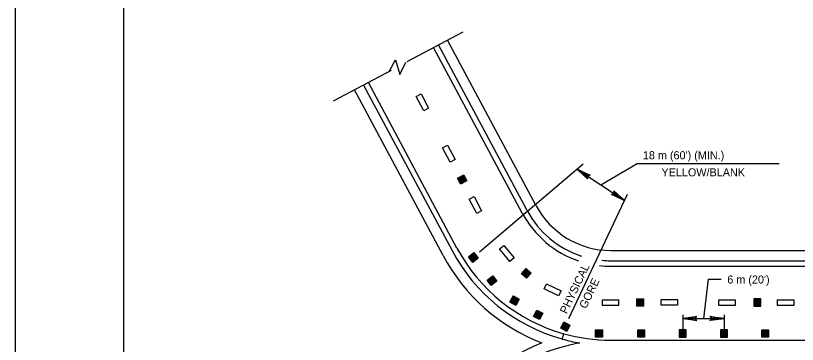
# Model space of a CAD drawing. Extents: x 639362 to 641108, y 298458 to 299646.
# Drawn here: x 639362.3 to 639652.3, y 299227.7 to 299349.9 of the extents above; entities that cross this region are included whole.
import ezdxf

# ---------------------------------------------------------------- set-up
doc = ezdxf.new("R2010")
doc.units = 0
for name, color, linetype in [('1', 7, 'Continuous'), ('2', 7, 'Continuous'), ('PLT-BNDY', 7, 'Continuous')]:
    doc.layers.add(name, color=color, linetype=linetype)

msp = doc.modelspace()

# ---------------------------------------------------------------- linework, layer by layer
at = {"layer": '1'}
msp.add_line((639402.31, 299630.63), (639402.31, 299066.63), dxfattribs=at)
at = {"layer": '2'}
for p, q in [((639507.56, 299332.75), (639528.33, 299343.84)), ((639555.38, 299279.23), (639522.52, 299340.74)), ((639550.22, 299276.47), (639517.36, 299337.98)), ((639552.04, 299277.45), (639519.18, 299338.95)), ((639480.23, 299318.14), (639501.69, 299329.61)), ((639493.13, 299325.03), (639491.31, 299324.06)), ((639491.31, 299324.06), (639524.18, 299262.56)), ((639526, 299263.53), (639493.13, 299325.03)), ((639520.84, 299260.77), (639487.97, 299322.28)), ((639510.86, 299319.82), (639512.69, 299320.78)), ((639513.67, 299314.5), (639510.86, 299319.82)), ((639512.69, 299320.78), (639515.49, 299315.46)), ((639515.49, 299315.46), (639513.67, 299314.5)), ((639520.7, 299300.75), (639522.53, 299301.71)), ((639523.5, 299295.43), (639520.7, 299300.75)), ((639522.53, 299301.71), (639525.33, 299296.39)), ((639525.33, 299296.39), (639523.5, 299295.43)), ((639534.31, 299262.09), (639572.85, 299294.76)), ((639579.34, 299287), (639592.87, 299294.89)), ((639592.87, 299294.89), (639645.57, 299294.89)), ((639526.16, 299289.48), (639528.5, 299290.73)), ((639526.36, 299289.38), (639528.47, 299290.51)), ((639528.47, 299290.51), (639529.48, 299288.63)), ((639528.5, 299290.73), (639529.68, 299288.53)), ((639570.58, 299292.84), (639588.1, 299281.16)), ((639527.34, 299287.28), (639526.16, 299289.48)), ((639527.37, 299287.5), (639526.36, 299289.38)), ((639526.6, 299289.3), (639528.4, 299290.27)), ((639527.44, 299287.74), (639526.6, 299289.3)), ((639526.84, 299289.23), (639528.33, 299290.03)), ((639527.51, 299287.98), (639526.84, 299289.23)), ((639527.08, 299289.16), (639528.25, 299289.79)), ((639527.58, 299288.22), (639527.08, 299289.16)), ((639527.32, 299289.09), (639528.18, 299289.55)), ((639527.66, 299288.46), (639527.32, 299289.09)), ((639529.68, 299288.53), (639527.34, 299287.28)), ((639529.48, 299288.63), (639527.37, 299287.5)), ((639529.24, 299288.7), (639527.44, 299287.74)), ((639529, 299288.78), (639527.51, 299287.98)), ((639527.56, 299289.01), (639528.11, 299289.31)), ((639527.73, 299288.7), (639527.56, 299289.01)), ((639528.76, 299288.85), (639527.58, 299288.22)), ((639528.52, 299288.92), (639527.66, 299288.46)), ((639528.28, 299288.99), (639527.73, 299288.7)), ((639528.04, 299289.07), (639527.8, 299288.94)), ((639528.11, 299289.31), (639528.28, 299288.99)), ((639528.18, 299289.55), (639528.52, 299288.92)), ((639528.25, 299289.79), (639528.76, 299288.85)), ((639528.33, 299290.03), (639529, 299288.78)), ((639528.4, 299290.27), (639529.24, 299288.7)), ((639530.53, 299281.68), (639532.36, 299282.65)), ((639532.36, 299282.65), (639535.16, 299277.33)), ((639567.44, 299237.37), (639589.2, 299283.5)), ((639533.34, 299276.36), (639530.53, 299281.68)), ((639535.16, 299277.33), (639533.34, 299276.36)), ((639530.27, 299260.24), (639532.21, 299261.81)), ((639530.5, 299260.26), (639532.15, 299261.6)), ((639532.15, 299261.6), (639533.66, 299259.74)), ((639532.21, 299261.81), (639533.88, 299259.75)), ((639583.1, 299262.59), (639743.31, 299262.59)), ((639531.94, 299258.18), (639530.27, 299260.24)), ((639532.01, 299258.4), (639530.5, 299260.26)), ((639530.75, 299260.23), (639532.13, 299261.35)), ((639532.03, 299258.65), (639530.75, 299260.23)), ((639531, 299260.21), (639532.1, 299261.1)), ((639532.06, 299258.9), (639531, 299260.21)), ((639531.25, 299260.18), (639532.07, 299260.85)), ((639532.08, 299259.14), (639531.25, 299260.18)), ((639531.5, 299260.15), (639532.05, 299260.6)), ((639532.11, 299259.39), (639531.5, 299260.15)), ((639531.75, 299260.13), (639532.02, 299260.35)), ((639532.14, 299259.64), (639531.75, 299260.13)), ((639533.88, 299259.75), (639531.94, 299258.18)), ((639531.99, 299260.1), (639532.16, 299259.89)), ((639533.66, 299259.74), (639532.01, 299258.4)), ((639532.02, 299260.35), (639532.41, 299259.87)), ((639533.41, 299259.77), (639532.03, 299258.65)), ((639532.05, 299260.6), (639532.66, 299259.84)), ((639533.16, 299259.79), (639532.06, 299258.9)), ((639532.07, 299260.85), (639532.91, 299259.81)), ((639532.91, 299259.81), (639532.08, 299259.14)), ((639532.1, 299261.1), (639533.16, 299259.79)), ((639532.66, 299259.84), (639532.11, 299259.39)), ((639532.13, 299261.35), (639533.41, 299259.77)), ((639532.41, 299259.87), (639532.14, 299259.64)), ((639583.09, 299258.81), (639743.31, 299258.81)), ((639549.93, 299253.95), (639551.72, 299255.91)), ((639550.15, 299253.92), (639551.77, 299255.69)), ((639551.72, 299255.91), (639553.56, 299254.22)), ((639551.77, 299255.69), (639553.34, 299254.25)), ((639583.09, 299256.74), (639743.31, 299256.74)), ((639537.18, 299251.59), (639539.3, 299253.19)), ((639537.39, 299251.52), (639539.31, 299252.96)), ((639539.3, 299253.19), (639540.8, 299251.19)), ((639539.31, 299252.96), (639540.59, 299251.26)), ((639551.77, 299252.27), (639549.93, 299253.95)), ((639551.72, 299252.48), (639550.15, 299253.92)), ((639550.41, 299253.93), (639551.78, 299255.44)), ((639551.71, 299252.74), (639550.41, 299253.93)), ((639550.65, 299253.94), (639551.79, 299255.19)), ((639551.7, 299252.99), (639550.65, 299253.94)), ((639550.9, 299253.96), (639551.8, 299254.94)), ((639551.69, 299253.24), (639550.9, 299253.96)), ((639551.15, 299253.97), (639551.81, 299254.69)), ((639551.68, 299253.49), (639551.15, 299253.97)), ((639551.41, 299253.98), (639551.83, 299254.43)), ((639551.67, 299253.74), (639551.41, 299253.98)), ((639551.84, 299254.19), (639551.66, 299253.99)), ((639552.09, 299254.19), (639551.67, 299253.74)), ((639552.34, 299254.21), (639551.68, 299253.49)), ((639552.59, 299254.22), (639551.69, 299253.24)), ((639552.84, 299254.23), (639551.7, 299252.99)), ((639553.09, 299254.24), (639551.71, 299252.74)), ((639553.34, 299254.25), (639551.72, 299252.48)), ((639553.56, 299254.22), (639551.77, 299252.27)), ((639551.78, 299255.44), (639553.09, 299254.24)), ((639551.79, 299255.19), (639552.84, 299254.23)), ((639551.8, 299254.94), (639552.59, 299254.22)), ((639551.81, 299254.69), (639552.34, 299254.21)), ((639551.83, 299254.43), (639552.09, 299254.19)), ((639538.68, 299249.6), (639537.18, 299251.59)), ((639538.67, 299249.82), (639537.39, 299251.52)), ((639537.64, 299251.49), (639539.27, 299252.72)), ((639538.71, 299250.07), (639537.64, 299251.49)), ((639537.89, 299251.45), (639539.24, 299252.47)), ((639538.74, 299250.32), (639537.89, 299251.45)), ((639538.14, 299251.42), (639539.2, 299252.22)), ((639538.78, 299250.57), (639538.14, 299251.42)), ((639538.39, 299251.39), (639539.16, 299251.97)), ((639538.81, 299250.82), (639538.39, 299251.39)), ((639538.63, 299251.35), (639539.13, 299251.72)), ((639538.85, 299251.07), (639538.63, 299251.35)), ((639540.59, 299251.26), (639538.67, 299249.82)), ((639540.8, 299251.19), (639538.68, 299249.6)), ((639540.33, 299251.3), (639538.71, 299250.07)), ((639540.09, 299251.34), (639538.74, 299250.32)), ((639539.84, 299251.37), (639538.78, 299250.57)), ((639539.59, 299251.4), (639538.81, 299250.82)), ((639539.34, 299251.44), (639538.85, 299251.07)), ((639538.88, 299251.31), (639539.1, 299251.47)), ((639539.13, 299251.72), (639539.34, 299251.44)), ((639539.16, 299251.97), (639539.59, 299251.4)), ((639539.2, 299252.22), (639539.84, 299251.37)), ((639539.24, 299252.47), (639540.09, 299251.34)), ((639539.27, 299252.72), (639540.33, 299251.3)), ((639558.31, 299248.37), (639559.21, 299250.23)), ((639559.21, 299250.23), (639564.62, 299247.61)), ((639619.18, 299251.99), (639617.48, 299237.38)), ((639619.18, 299251.99), (639624.04, 299251.99)), ((639563.72, 299245.75), (639558.31, 299248.37)), ((639564.62, 299247.61), (639563.72, 299245.75)), ((639545.66, 299243.42), (639546.95, 299245.74)), ((639545.88, 299243.45), (639547.05, 299245.54)), ((639546.12, 299243.52), (639547.12, 299245.3)), ((639546.36, 299243.59), (639547.19, 299245.06)), ((639546.6, 299243.65), (639547.25, 299244.82)), ((639546.84, 299243.72), (639547.32, 299244.58)), ((639546.95, 299245.74), (639549.13, 299244.52)), ((639547.05, 299245.54), (639548.91, 299244.5)), ((639547.09, 299243.79), (639547.39, 299244.33)), ((639547.12, 299245.3), (639548.66, 299244.43)), ((639547.19, 299245.06), (639548.42, 299244.37)), ((639547.25, 299244.82), (639548.18, 299244.3)), ((639547.32, 299244.58), (639547.94, 299244.23)), ((639547.33, 299243.86), (639547.46, 299244.09)), ((639547.39, 299244.33), (639547.7, 299244.16)), ((639547.7, 299244.16), (639547.4, 299243.62)), ((639547.94, 299244.23), (639547.47, 299243.38)), ((639548.18, 299244.3), (639547.53, 299243.13)), ((639548.42, 299244.37), (639547.6, 299242.89)), ((639548.66, 299244.43), (639547.67, 299242.65)), ((639548.91, 299244.5), (639547.74, 299242.41)), ((639549.13, 299244.52), (639547.83, 299242.2)), ((639592.74, 299244.59), (639595.23, 299244.59)), ((639592.74, 299241.93), (639592.74, 299244.59)), ((639592.92, 299244.45), (639595.05, 299244.45)), ((639592.92, 299242.06), (639592.92, 299244.45)), ((639593.1, 299244.28), (639594.87, 299244.28)), ((639593.1, 299242.24), (639593.1, 299244.28)), ((639593.28, 299244.1), (639594.7, 299244.1)), ((639593.28, 299242.41), (639593.28, 299244.1)), ((639594.7, 299244.1), (639594.7, 299242.41)), ((639594.87, 299244.28), (639594.87, 299242.24)), ((639595.05, 299244.45), (639595.05, 299242.06)), ((639595.23, 299244.59), (639595.23, 299241.93)), ((639601.74, 299242.34), (639601.74, 299244.4)), ((639601.74, 299244.4), (639607.75, 299244.4)), ((639607.75, 299244.4), (639607.75, 299242.34)), ((639623.19, 299242.15), (639623.19, 299244.22)), ((639623.19, 299244.22), (639629.21, 299244.22)), ((639629.21, 299244.22), (639629.21, 299242.15)), ((639638.65, 299244.59), (639636.15, 299244.59)), ((639636.15, 299244.59), (639636.15, 299241.93)), ((639638.46, 299244.45), (639636.33, 299244.45)), ((639636.33, 299244.45), (639636.33, 299242.06)), ((639638.28, 299244.28), (639636.51, 299244.28)), ((639636.51, 299244.28), (639636.51, 299242.24)), ((639638.1, 299244.1), (639636.69, 299244.1)), ((639636.69, 299244.1), (639636.69, 299242.41)), ((639638.1, 299242.41), (639638.1, 299244.1)), ((639638.28, 299242.24), (639638.28, 299244.28)), ((639638.46, 299242.06), (639638.46, 299244.45)), ((639638.65, 299241.93), (639638.65, 299244.59)), ((639644.92, 299242.15), (639644.92, 299244.22)), ((639644.92, 299244.22), (639650.93, 299244.22)), ((639650.93, 299244.22), (639650.93, 299242.15)), ((639547.83, 299242.2), (639545.66, 299243.42)), ((639547.74, 299242.41), (639545.88, 299243.45)), ((639547.67, 299242.65), (639546.12, 299243.52)), ((639547.6, 299242.89), (639546.36, 299243.59)), ((639547.53, 299243.13), (639546.6, 299243.65)), ((639547.47, 299243.38), (639546.84, 299243.72)), ((639547.4, 299243.62), (639547.09, 299243.79)), ((639595.23, 299241.93), (639592.74, 299241.93)), ((639595.05, 299242.06), (639592.92, 299242.06)), ((639594.87, 299242.24), (639593.1, 299242.24)), ((639594.7, 299242.41), (639593.28, 299242.41)), ((639593.45, 299243.92), (639594.52, 299243.92)), ((639593.45, 299242.59), (639593.45, 299243.92)), ((639594.52, 299242.59), (639593.45, 299242.59)), ((639593.63, 299242.77), (639593.63, 299243.74)), ((639593.63, 299243.74), (639594.34, 299243.74)), ((639594.34, 299242.77), (639593.63, 299242.77)), ((639593.81, 299243.57), (639594.17, 299243.57)), ((639593.81, 299242.95), (639593.81, 299243.57)), ((639594.17, 299242.95), (639593.81, 299242.95)), ((639593.99, 299243.39), (639593.99, 299243.12)), ((639594.17, 299243.57), (639594.17, 299242.95)), ((639594.34, 299243.74), (639594.34, 299242.77)), ((639594.52, 299243.92), (639594.52, 299242.59)), ((639607.75, 299242.34), (639601.74, 299242.34)), ((639629.21, 299242.15), (639623.19, 299242.15)), ((639636.15, 299241.93), (639638.65, 299241.93)), ((639636.33, 299242.06), (639638.46, 299242.06)), ((639636.51, 299242.24), (639638.28, 299242.24)), ((639636.69, 299242.41), (639638.1, 299242.41)), ((639637.93, 299243.92), (639636.86, 299243.92)), ((639636.86, 299243.92), (639636.86, 299242.59)), ((639636.86, 299242.59), (639637.93, 299242.59)), ((639637.04, 299243.74), (639637.04, 299242.77)), ((639637.75, 299243.74), (639637.04, 299243.74)), ((639637.04, 299242.77), (639637.75, 299242.77)), ((639637.57, 299243.57), (639637.22, 299243.57)), ((639637.22, 299243.57), (639637.22, 299242.95)), ((639637.22, 299242.95), (639637.57, 299242.95)), ((639637.4, 299243.39), (639637.4, 299243.12)), ((639637.57, 299242.95), (639637.57, 299243.57)), ((639637.75, 299242.77), (639637.75, 299243.74)), ((639637.93, 299242.59), (639637.93, 299243.92)), ((639650.93, 299242.15), (639644.92, 299242.15)), ((639554.44, 299238.06), (639555.65, 299240.43)), ((639554.66, 299238.1), (639555.76, 299240.23)), ((639554.9, 299238.17), (639555.83, 299239.99)), ((639555.14, 299238.25), (639555.91, 299239.75)), ((639556.4, 299237.61), (639555.14, 299238.25)), ((639555.38, 299238.33), (639555.99, 299239.51)), ((639556.33, 299237.84), (639555.38, 299238.33)), ((639555.62, 299238.41), (639556.06, 299239.28)), ((639556.25, 299238.08), (639555.62, 299238.41)), ((639555.65, 299240.43), (639557.87, 299239.29)), ((639555.76, 299240.23), (639557.65, 299239.26)), ((639555.83, 299239.99), (639557.41, 299239.18)), ((639555.86, 299238.48), (639556.14, 299239.04)), ((639556.17, 299238.32), (639555.86, 299238.48)), ((639555.91, 299239.75), (639557.17, 299239.11)), ((639555.99, 299239.51), (639556.93, 299239.03)), ((639556.06, 299239.28), (639556.7, 299238.95)), ((639556.1, 299238.56), (639556.22, 299238.8)), ((639556.14, 299239.04), (639556.45, 299238.87)), ((639556.45, 299238.87), (639556.17, 299238.32)), ((639556.7, 299238.95), (639556.25, 299238.08)), ((639556.93, 299239.03), (639556.33, 299237.84)), ((639557.17, 299239.11), (639556.4, 299237.61)), ((639557.41, 299239.18), (639556.48, 299237.37)), ((639557.65, 299239.26), (639556.56, 299237.13)), ((639557.87, 299239.29), (639556.66, 299236.93)), ((639609.74, 299238.7), (639609.74, 299232.09)), ((639625.08, 299238.7), (639625.08, 299232.09)), ((639556.66, 299236.93), (639554.44, 299238.06)), ((639556.56, 299237.13), (639554.66, 299238.1)), ((639556.48, 299237.37), (639554.9, 299238.17)), ((639564.49, 299233.7), (639565.7, 299236.06)), ((639564.71, 299233.73), (639565.8, 299235.87)), ((639564.95, 299233.81), (639565.88, 299235.63)), ((639565.19, 299233.89), (639565.96, 299235.39)), ((639565.7, 299236.06), (639567.92, 299234.92)), ((639565.8, 299235.87), (639567.7, 299234.9)), ((639565.88, 299235.63), (639567.46, 299234.82)), ((639565.96, 299235.39), (639567.22, 299234.74)), ((639609.74, 299237.38), (639625.08, 299237.38)), ((639566.71, 299232.56), (639564.49, 299233.7)), ((639566.61, 299232.76), (639564.71, 299233.73)), ((639566.53, 299233), (639564.95, 299233.81)), ((639566.45, 299233.24), (639565.19, 299233.89)), ((639565.43, 299233.96), (639566.04, 299235.15)), ((639566.38, 299233.48), (639565.43, 299233.96)), ((639565.67, 299234.04), (639566.11, 299234.91)), ((639566.3, 299233.72), (639565.67, 299234.04)), ((639565.91, 299234.12), (639566.19, 299234.67)), ((639566.22, 299233.96), (639565.91, 299234.12)), ((639566.04, 299235.15), (639566.98, 299234.66)), ((639566.11, 299234.91), (639566.75, 299234.59)), ((639566.15, 299234.2), (639566.27, 299234.43)), ((639566.19, 299234.67), (639566.5, 299234.51)), ((639566.5, 299234.51), (639566.22, 299233.96)), ((639566.75, 299234.59), (639566.3, 299233.72)), ((639566.98, 299234.66), (639566.38, 299233.48)), ((639567.22, 299234.74), (639566.45, 299233.24)), ((639567.46, 299234.82), (639566.53, 299233)), ((639567.7, 299234.9), (639566.61, 299232.76)), ((639567.92, 299234.92), (639566.71, 299232.56)), ((639577.44, 299230.43), (639577.44, 299233.09)), ((639577.44, 299233.09), (639579.94, 299233.09)), ((639577.62, 299230.57), (639577.62, 299232.96)), ((639577.62, 299232.96), (639579.75, 299232.96)), ((639577.8, 299230.74), (639577.8, 299232.78)), ((639577.8, 299232.78), (639579.57, 299232.78)), ((639577.98, 299230.92), (639577.98, 299232.61)), ((639577.98, 299232.61), (639579.4, 299232.61)), ((639579.4, 299232.61), (639579.4, 299230.92)), ((639579.57, 299232.78), (639579.57, 299230.74)), ((639579.75, 299232.96), (639579.75, 299230.57)), ((639579.94, 299233.09), (639579.94, 299230.43)), ((639593.04, 299230.43), (639593.04, 299233.09)), ((639593.04, 299233.09), (639595.54, 299233.09)), ((639593.23, 299230.57), (639593.23, 299232.96)), ((639593.23, 299232.96), (639595.35, 299232.96)), ((639593.4, 299230.74), (639593.4, 299232.78)), ((639593.4, 299232.78), (639595.18, 299232.78)), ((639593.58, 299230.92), (639593.58, 299232.61)), ((639593.58, 299232.61), (639595, 299232.61)), ((639595, 299232.61), (639595, 299230.92)), ((639595.18, 299232.78), (639595.18, 299230.74)), ((639595.35, 299232.96), (639595.35, 299230.57)), ((639595.54, 299233.09), (639595.54, 299230.43)), ((639610.97, 299233.09), (639608.47, 299233.09)), ((639608.47, 299233.09), (639608.47, 299230.43)), ((639610.79, 299232.96), (639608.66, 299232.96)), ((639608.66, 299232.96), (639608.66, 299230.57)), ((639610.61, 299232.78), (639608.84, 299232.78)), ((639608.84, 299232.78), (639608.84, 299230.74)), ((639610.43, 299232.61), (639609.01, 299232.61)), ((639609.01, 299232.61), (639609.01, 299230.92)), ((639610.43, 299230.92), (639610.43, 299232.61)), ((639610.61, 299230.74), (639610.61, 299232.78)), ((639610.79, 299230.57), (639610.79, 299232.96)), ((639610.97, 299230.43), (639610.97, 299233.09)), ((639626.31, 299233.09), (639623.81, 299233.09)), ((639623.81, 299233.09), (639623.81, 299230.43)), ((639626.12, 299232.96), (639623.99, 299232.96)), ((639623.99, 299232.96), (639623.99, 299230.57)), ((639625.95, 299232.78), (639624.17, 299232.78)), ((639624.17, 299232.78), (639624.17, 299230.74)), ((639625.77, 299232.61), (639624.35, 299232.61)), ((639624.35, 299232.61), (639624.35, 299230.92)), ((639625.77, 299230.92), (639625.77, 299232.61)), ((639625.95, 299230.74), (639625.95, 299232.78)), ((639626.12, 299230.57), (639626.12, 299232.96)), ((639626.31, 299230.43), (639626.31, 299233.09)), ((639639.06, 299230.43), (639639.06, 299233.09)), ((639639.06, 299233.09), (639641.55, 299233.09)), ((639639.24, 299230.57), (639639.24, 299232.96)), ((639639.24, 299232.96), (639641.37, 299232.96)), ((639639.42, 299230.74), (639639.42, 299232.78)), ((639639.42, 299232.78), (639641.19, 299232.78)), ((639639.6, 299230.92), (639639.6, 299232.61)), ((639639.6, 299232.61), (639641.01, 299232.61)), ((639641.01, 299232.61), (639641.01, 299230.92)), ((639641.19, 299232.78), (639641.19, 299230.74)), ((639641.37, 299232.96), (639641.37, 299230.57)), ((639641.55, 299233.09), (639641.55, 299230.43)), ((639565.05, 299229.71), (639565.61, 299231.69)), ((639579.94, 299230.43), (639577.44, 299230.43)), ((639579.75, 299230.57), (639577.62, 299230.57)), ((639579.57, 299230.74), (639577.8, 299230.74)), ((639579.4, 299230.92), (639577.98, 299230.92)), ((639578.16, 299231.1), (639578.16, 299232.43)), ((639578.16, 299232.43), (639579.22, 299232.43)), ((639579.22, 299231.1), (639578.16, 299231.1)), ((639578.33, 299231.28), (639578.33, 299232.25)), ((639578.33, 299232.25), (639579.04, 299232.25)), ((639579.04, 299231.28), (639578.33, 299231.28)), ((639578.51, 299231.45), (639578.51, 299232.07)), ((639578.51, 299232.07), (639578.86, 299232.07)), ((639578.86, 299231.45), (639578.51, 299231.45)), ((639578.69, 299231.63), (639578.69, 299231.9)), ((639578.86, 299232.07), (639578.86, 299231.45)), ((639579.04, 299232.25), (639579.04, 299231.28)), ((639579.22, 299232.43), (639579.22, 299231.1)), ((639595.54, 299230.43), (639593.04, 299230.43)), ((639595.35, 299230.57), (639593.23, 299230.57)), ((639595.18, 299230.74), (639593.4, 299230.74)), ((639595, 299230.92), (639593.58, 299230.92)), ((639593.76, 299231.1), (639593.76, 299232.43)), ((639593.76, 299232.43), (639594.82, 299232.43)), ((639594.82, 299231.1), (639593.76, 299231.1)), ((639593.93, 299231.28), (639593.93, 299232.25)), ((639593.93, 299232.25), (639594.65, 299232.25)), ((639594.65, 299231.28), (639593.93, 299231.28)), ((639594.11, 299231.45), (639594.11, 299232.07)), ((639594.11, 299232.07), (639594.47, 299232.07)), ((639594.47, 299231.45), (639594.11, 299231.45)), ((639594.29, 299231.63), (639594.29, 299231.9)), ((639594.47, 299232.07), (639594.47, 299231.45)), ((639594.65, 299232.25), (639594.65, 299231.28)), ((639594.82, 299232.43), (639594.82, 299231.1)), ((639608.47, 299230.43), (639610.97, 299230.43)), ((639608.66, 299230.57), (639610.79, 299230.57)), ((639608.84, 299230.74), (639610.61, 299230.74)), ((639609.01, 299230.92), (639610.43, 299230.92)), ((639610.25, 299232.43), (639609.19, 299232.43)), ((639609.19, 299232.43), (639609.19, 299231.1)), ((639609.19, 299231.1), (639610.25, 299231.1)), ((639610.08, 299232.25), (639609.37, 299232.25)), ((639609.37, 299232.25), (639609.37, 299231.28)), ((639609.37, 299231.28), (639610.08, 299231.28)), ((639609.9, 299232.07), (639609.55, 299232.07)), ((639609.55, 299232.07), (639609.55, 299231.45)), ((639609.55, 299231.45), (639609.9, 299231.45)), ((639609.72, 299231.63), (639609.72, 299231.9)), ((639609.9, 299231.45), (639609.9, 299232.07)), ((639610.08, 299231.28), (639610.08, 299232.25)), ((639610.25, 299231.1), (639610.25, 299232.43)), ((639623.81, 299230.43), (639626.31, 299230.43)), ((639623.99, 299230.57), (639626.12, 299230.57)), ((639624.17, 299230.74), (639625.95, 299230.74)), ((639624.35, 299230.92), (639625.77, 299230.92)), ((639625.59, 299232.43), (639624.53, 299232.43)), ((639624.53, 299232.43), (639624.53, 299231.1)), ((639624.53, 299231.1), (639625.59, 299231.1)), ((639625.42, 299232.25), (639624.7, 299232.25)), ((639624.7, 299232.25), (639624.7, 299231.28)), ((639624.7, 299231.28), (639625.42, 299231.28)), ((639625.24, 299232.07), (639624.88, 299232.07)), ((639624.88, 299232.07), (639624.88, 299231.45)), ((639624.88, 299231.45), (639625.24, 299231.45)), ((639625.06, 299231.63), (639625.06, 299231.9)), ((639625.24, 299231.45), (639625.24, 299232.07)), ((639625.42, 299231.28), (639625.42, 299232.25)), ((639625.59, 299231.1), (639625.59, 299232.43)), ((639641.55, 299230.43), (639639.06, 299230.43)), ((639641.37, 299230.57), (639639.24, 299230.57)), ((639641.19, 299230.74), (639639.42, 299230.74)), ((639641.01, 299230.92), (639639.6, 299230.92)), ((639639.77, 299231.1), (639639.77, 299232.43)), ((639639.77, 299232.43), (639640.84, 299232.43)), ((639640.84, 299231.1), (639639.77, 299231.1)), ((639639.95, 299231.28), (639639.95, 299232.25)), ((639639.95, 299232.25), (639640.66, 299232.25)), ((639640.66, 299231.28), (639639.95, 299231.28)), ((639640.13, 299231.45), (639640.13, 299232.07)), ((639640.13, 299232.07), (639640.48, 299232.07)), ((639640.48, 299231.45), (639640.13, 299231.45)), ((639640.3, 299231.63), (639640.3, 299231.9)), ((639640.48, 299232.07), (639640.48, 299231.45)), ((639640.66, 299232.25), (639640.66, 299231.28)), ((639640.84, 299232.43), (639640.84, 299231.1)), ((639583.05, 299229.28), (639672.74, 299229.28))]:
    msp.add_line(p, q, dxfattribs=at)
for points in [[(639501.02, 299329.35), (639503.25, 299333.42), (639504.81, 299328), (639507.1, 299332.53)], [(639574.39, 299289.55), (639574.43, 299289.95), (639570.58, 299292.84), (639574.39, 299289.55), (639574.48, 299289.22), (639570.58, 299292.84), (639574.71, 299290.37), (639575.05, 299290.57), (639570.58, 299292.84), (639575.41, 299290.62), (639575.05, 299290.57)], [(639584.29, 299284.45), (639584.24, 299284.05), (639588.1, 299281.16), (639584.29, 299284.45), (639584.2, 299284.78), (639588.1, 299281.16), (639583.97, 299283.63), (639583.62, 299283.43), (639588.1, 299281.16), (639583.27, 299283.38), (639583.62, 299283.43)], [(639614.74, 299236.75), (639614.55, 299237.11), (639609.74, 299237.38), (639614.74, 299236.75), (639614.99, 299236.53), (639609.74, 299237.38), (639614.55, 299237.62), (639614.72, 299237.97), (639609.74, 299237.38), (639614.99, 299238.21), (639614.72, 299237.97)], [(639620.08, 299238), (639620.27, 299237.64), (639625.08, 299237.38), (639620.08, 299238), (639619.83, 299238.22), (639625.08, 299237.38), (639620.27, 299237.14), (639620.1, 299236.78), (639625.08, 299237.38), (639619.83, 299236.54), (639620.1, 299236.78)]]:
    msp.add_lwpolyline(points, dxfattribs=at)
for points in [[(639541.8, 299263.21), (639543.4, 299264.52), (639547.21, 299259.86), (639545.61, 299258.56)], [(639579.96, 299244.22), (639585.97, 299244.22), (639585.97, 299242.15), (639579.96, 299242.15)]]:
    msp.add_lwpolyline(points, close=True, dxfattribs=at)
for centre, radius, start, end in [((639583.13, 299294.06), 31.46, 208.1179, 269.9284), ((639583.13, 299294.06), 37.31, 208.1179, 251.2489), ((639583.13, 299294.06), 35.25, 208.1179, 251.9444), ((639583.13, 299294.06), 66.85, 208.1179, 254.2131), ((639583.13, 299294.06), 64.78, 208.1179, 254.3067), ((639583.13, 299294.06), 70.63, 208.1179, 248.7197), ((639583.13, 299294.06), 35.25, 264.5437, 269.9284), ((639583.13, 299294.06), 37.31, 263.3923, 269.9284), ((639583.13, 299294.06), 66.85, 254.3067, 259.9292), ((639583.13, 299294.06), 64.78, 254.3067, 269.9284), ((639583.13, 299162.43), 70.63, 111.2803, 151.8821), ((639583.13, 299162.43), 66.85, 100.0708, 151.8821)]:
    msp.add_arc(centre, radius, start, end, dxfattribs=at)
at = {"layer": 'PLT-BNDY'}
msp.add_lwpolyline([(639362.31, 299645.63), (640203.31, 299645.63), (640203.31, 299051.63), (639362.31, 299051.63)], close=True, dxfattribs=at)

# ---------------------------------------------------------------- texts
at = {"layer": '2'}
for s, p in [("18 m (60') (MIN.)", (639594.96, 299296.49)), ('YELLOW/BLANK', (639601.85, 299290.14)), ("6 m (20')", (639626.27, 299250.31))]:
    msp.add_text(s, height=3, dxfattribs=at).set_placement(p)
for s, p in [('PHYSICAL', (639566.7, 299238.83)), ('GORE', (639573.89, 299240.74))]:
    msp.add_text(s, height=3, rotation=64.3716, dxfattribs=at).set_placement(p)

doc.saveas('drawing.dxf')
